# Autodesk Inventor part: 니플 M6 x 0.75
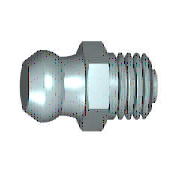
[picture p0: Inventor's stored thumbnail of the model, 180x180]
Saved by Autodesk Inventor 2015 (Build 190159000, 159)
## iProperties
IsCustomPart: 1
Created: 2012-02
Part Number: 니플 M6 x 0.75
Material: 강철, 연강
Description: 윤활 니플, 원추 유형 A
Document SubType Name: Modeling
Standard: JIS B 1575
Designer: mduedu
Standards Organization: JIS
Language: ko-KR
Size Designation: MT 6 x 0.75
Categories: <MemberInstance><Categories><Category DisplayName="기타 부품" InternalName="5aa15e00-363f-49f2-933f-16f664388e3f" Mnemonic="OTHER"><Category DisplayName="그리스 부속품" I
Density: 7.86 g/cm^3
Mass: 3.2546 g
Surface Area: 3.29319 cm^2
Volume: 0.414071 cm^3
Appearance: 금색
Author: mduedu
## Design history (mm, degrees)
sketch "스케치1"
  geometry: L1 (-8.8, 0)-(-8.8, 2.4); L2 (-8.8, 2.4)-(-7.335, 3.202); L3 (-8.8, 0)-(4.7, 0); L4 (4.7, 0)-(4.7, 1.5); L5 (4.7, 1.5)-(4, 1.5); L6 (4, 1.5)-(4, 3); L7 (4, 3)-(0, 3); L8 (-11.5, 0)-(7.4, 0) reference; L9 (0, -1.733)-(0, 10.398) reference; L10 (-3, 3.5)-(0, 3.5); L11 (0, 3.5)-(0, 3); A1 r 3.3 centre (-6.535, 0) between (-4.789, 2.8) and (-7.335, 3.202); A2 r 6 centre (-6.053, 8.665) between (-4.789, 2.8) and (-3, 3.5)
  constraints: 18 end point, 5 perpendicular, 4 point on circle, 2 centre point, 2 parallel, 2 point on line, 1 collinear, 1 vertical
  dimensions: "d0" = 13.5 distance between parallel lines of L1 L4 (= GL); "d1" = 5.6 diameter of A1.start L3 (= KGB2); "d2" = 0.7 distance between parallel lines of L4 L6 (= PHH); "d3" = 3 diameter of L5 L3 (= 0.5 x NND); "d4" = 6 diameter of L7 L3 (= NND); "d5" = 6.6 dimension on A1 L3 (= KR); "d6" = 4.8 diameter of L1.end L3 (= KGB1); "d7" = 6 radius of A2 (= RBN); "d11" = 7 diameter of L10.start L3 (= SW); "d14" = 3 distance of L10.start L10.end (= KOH); "d15" = 4 distance between parallel lines of L6 L11 (= NLG); "d61" = 7.33505 distance from line of L9 L2.end (computed from KGB1, KR, PHH, GL, NLG, VERS); "d62" = 6.53505 distance from line of L9 A1.centre (computed from NLG, GL, PHH, KR, KGB1)
revolve "본체" sketch "스케치1" stored, may be unused: angle "d25" = 90 deg
sketch "스케치2"
  geometry: L1 (2.021, 3.5)-(4.041, 0); L2 (4.041, 0)-(2.021, -3.5); L3 (2.021, -3.5)-(-2.021, -3.5); L4 (-2.021, -3.5)-(-4.041, 0); L5 (-4.041, 0)-(-2.021, 3.5); L6 (-2.021, 3.5)-(2.021, 3.5); C1 r 3.5 at (0, 0) reference; 1 further point
  constraints: 12 end point, 1 coincident, 1 horizontal, 1 tangent, 11 other
extrude "머리" join sketch "스케치2" distance "d17" = 3 (= KOH); taper "d18" = 0 deg
sketch "스케치3"
  geometry: L1 (2.687, 4.041)-(3, 4.041); L2 (3, 4.041)-(3, 3.5); L3 (3, 3.5)-(2.687, 4.041); L4 (0.313, 4.041)-(0, 4.041); L5 (0, 4.041)-(0, 3.5); L6 (0, 3.5)-(0.313, 4.041); L7 (3.6, 0)-(-0.6, 0) reference; L8 (0, 4.041)-(0, 2.021) reference; L9 (0, 4.041)-(3, 4.041) reference; L10 (3, 3.031)-(3, 4.041) reference
  constraints: 12 end point, 4 collinear, 3 perpendicular, 1 horizontal
  dimensions: "d19" = 3.5 distance from line of L5.end L7 (= 0.5 x SW); "d20" = 3.5 distance from line of L2.end L7 (= 0.5 x SW); "d21" = 30 deg angle of L6 L5; "d22" = 30 deg angle of L2 L3
revolve "모따기1" sketch "스케치3" stored, may be unused: angle "d56" = 90 deg
body "Solid1"
fillet "모깎기1" dims "d8" = 0.2 (= RR)
feature "스레드1" dims "d9" = 3.53991 (= NLG - GAL), "d10" = 0
chamfer "모따기2" distance "d23" = 0.46009 (= -0.5 x GD1 + 0.5 x NND); stored, may be unused: angle "d24" = 45 deg, second distance "d59" = 0.46009 (= -0.5 x GD1 + 0.5 x NND)
other parameters: "NLG" = 4 [user parameter; used in 4 equation terms], "GL" = 13.5 [user parameter; used in 3 equation terms], "NND" = 6 [user parameter; used in 4 equation terms], "KGB1" = 4.8 [user parameter; used in 3 equation terms], "KGB2" = 5.6 [user parameter; used in 1 equation term], "VERS" = 0.8 [user parameter; used in 1 equation term], "KR" = 6.6 [user parameter; used in 3 equation terms], "RBN" = 6 [user parameter; used in 1 equation term], "SW" = 7 [user parameter; used in 3 equation terms], "KOH" = 3 [user parameter; used in 2 equation terms], "GAL" = 0.46009 (= 0.61345 x PTC) [user parameter; used in 1 equation term], "FAWI" = 45 deg [user parameter], "PHH" = 0.7 [user parameter; used in 3 equation terms], "GD1" = 5.07983 (= THREADDIA - 1.2269 x PTC) [user parameter; used in 2 equation terms], "RR" = 0.2 [user parameter; used in 1 equation term], "d12" = 0, "d13" = 0, "GUL" = 0.46009 (= 0.61345 x PTC) [user parameter], "TPU" = 13.33333 (computed from PTC) [user parameter], "DULO" = 1.5 [user parameter], "PTC" = 0.75 [user parameter; used in 4 equation terms], "GEL" = 4 [user parameter], "THREADDIA" = 6 [user parameter; used in 1 equation term], "TOA" = 30 deg [user parameter]
